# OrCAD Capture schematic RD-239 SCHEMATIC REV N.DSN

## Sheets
1 PAGE2: size A
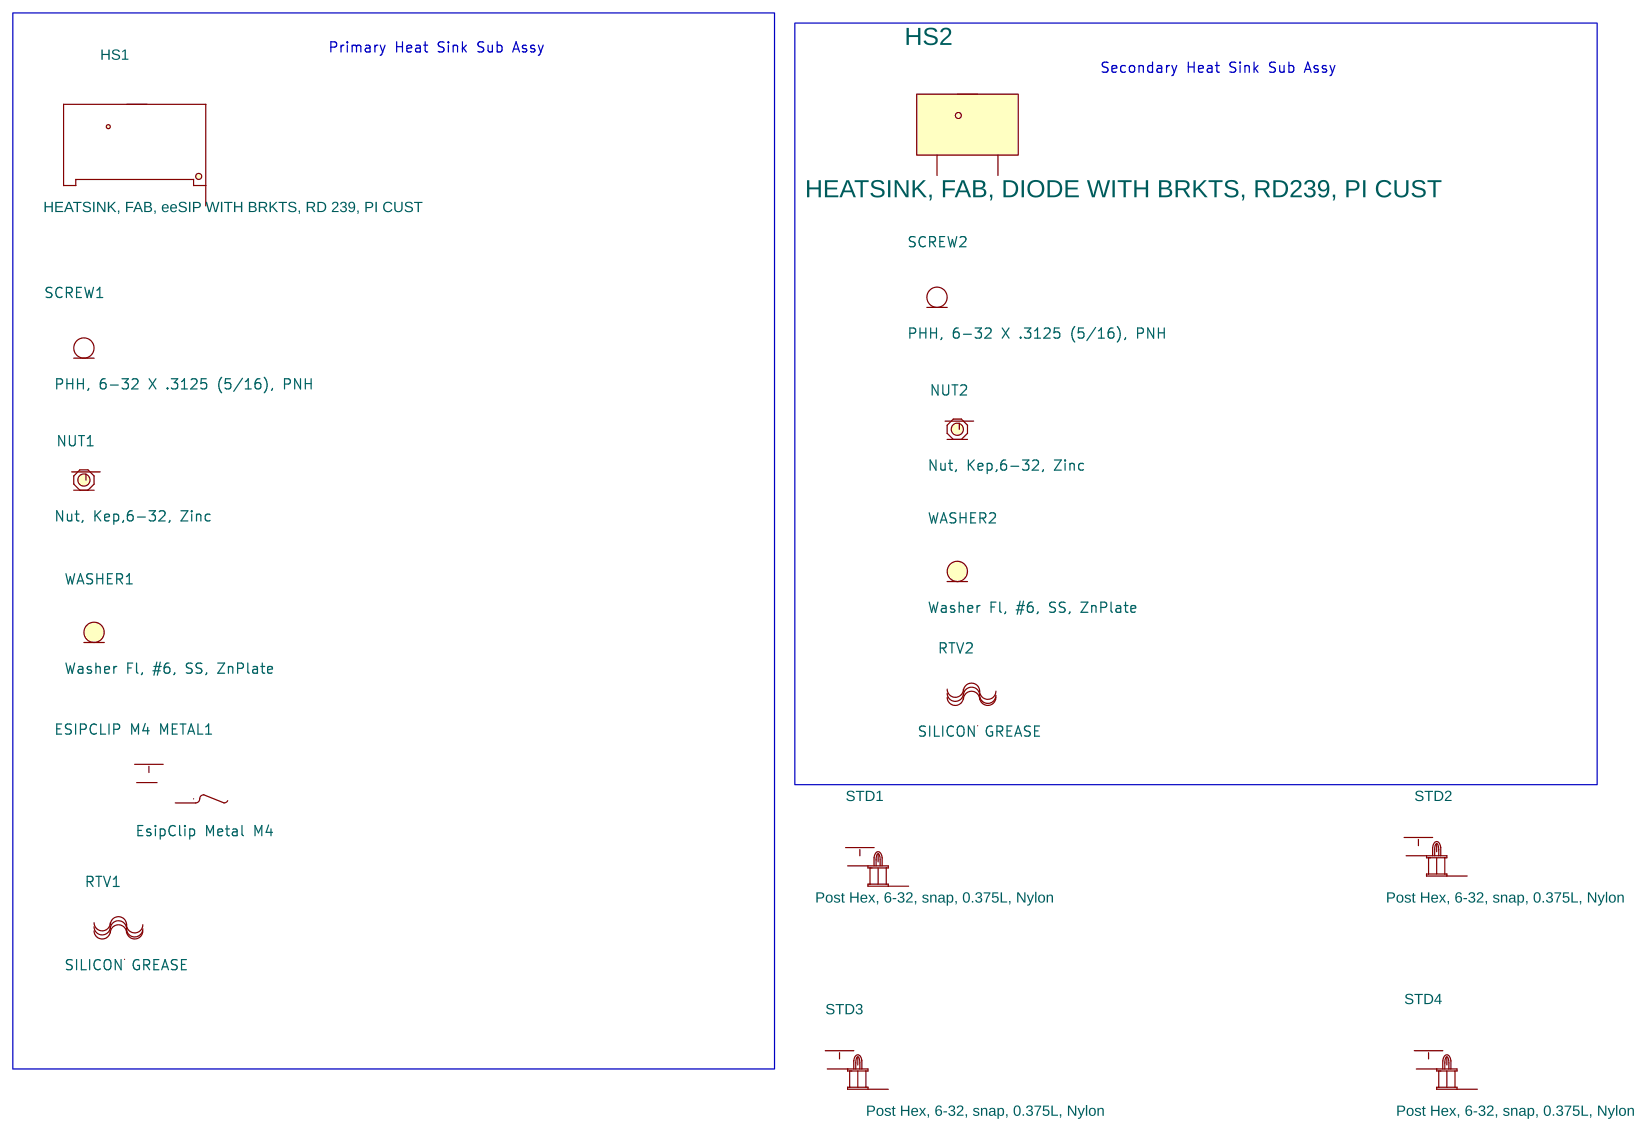
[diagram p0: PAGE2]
2 PAGE1: size B
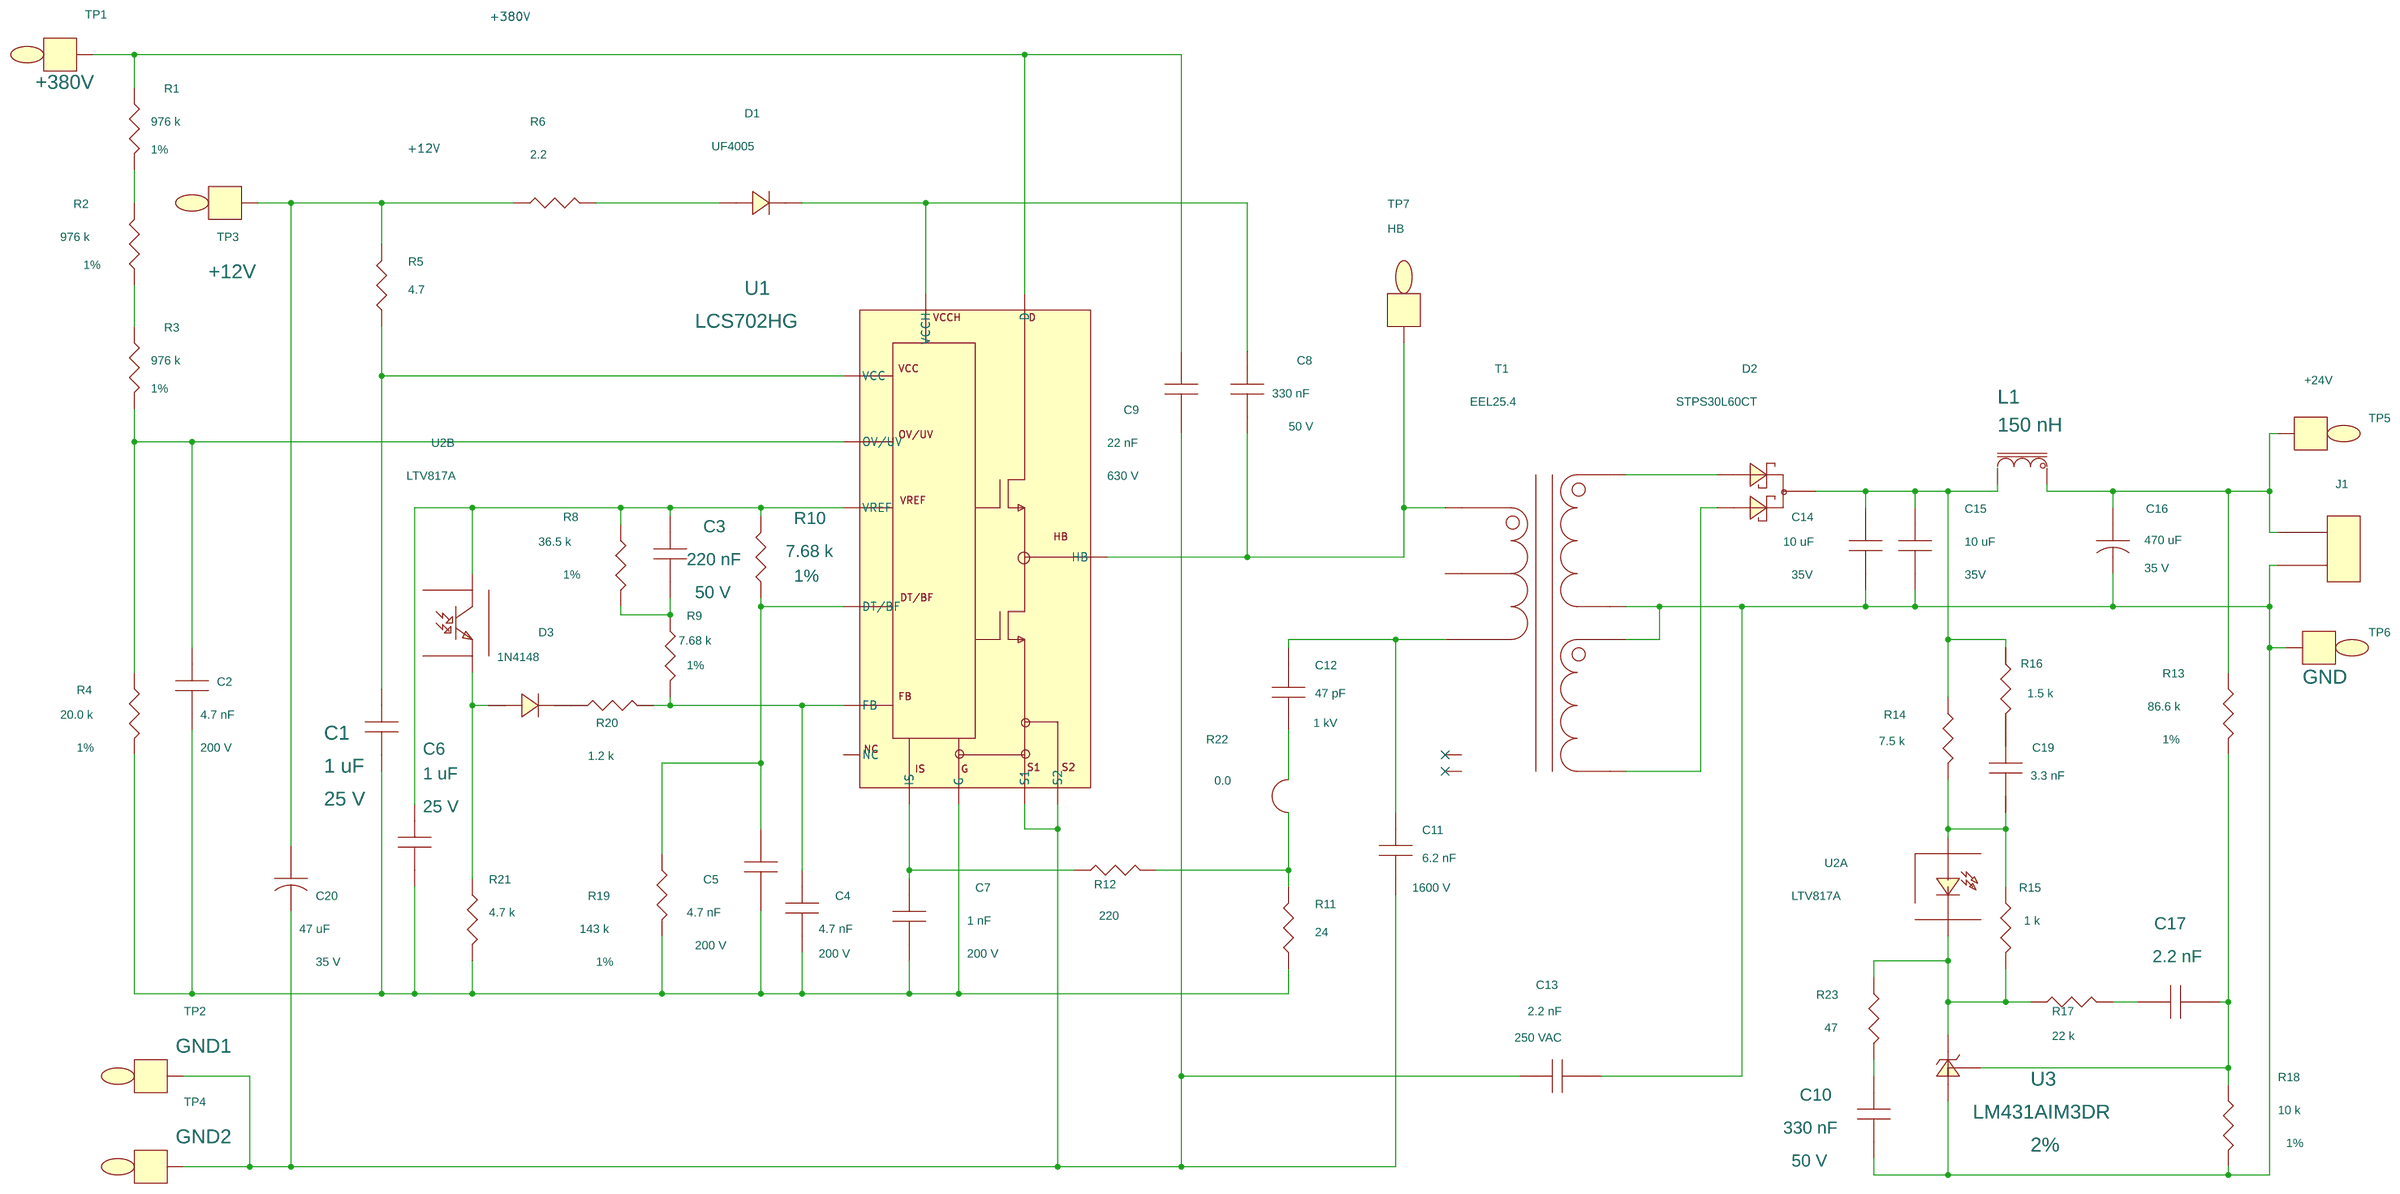
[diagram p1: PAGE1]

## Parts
sheet PAGE1
C1  1 uF  [pismc1206]
C2  4.7 nF  [pismc0805]
C3  220 nF  [pismc1206]
C4  4.7 nF  [pismc0805]
C5  4.7 nF  [pismc0805]
C6  1 uF  [pismc1206]
C7  1 nF  [pismc0805]
C8  330 nF  [pinpcaprad200x100200030]
C9  22 nF  [pismc1210]
C10  330 nF  [pinpcaprad200x100200030]
C11  6.2 nF  [PI_NP_CAPRAD709X197LS590D050]
C12  47 pF  [pinpcaprad180x160200030]
C13  2.2 nF  [pinpycaprad540x290ls400040]
C14  10 uF  [pismc1210]
C15  10 uF  [pismc1210]
C16  470 uF  [PI_POLCAP_CYL/D.400/LS.200/.040]
C17  2.2 nF  [pismc0805]
C19  3.3 nF  [PI_SM/C_0805]
C20  47 uF  [pipolcapclyd200ls80030]
D1  UF4005  [pidv200x110x040do41]
D2  STPS30L60CT
D3  1N4148  [PI_DAX/.375X.070/.030/DO_35]
J1  CON3
L1  150 nH  [PI_TOROID_2P_.150X.320/LS.150WX.150LX.050]
R1  976 k  [pismr1206]
R2  976 k  [pismr1206]
R3  976 k  [pi14wvresd100ls100d030]
R4  20.0 k  [pismr0805]
R5  4.7  [PI_SM/R_1206]
R6  2.2  [pismr1206]
R8  36.5 k  [pismr1206]
R9  7.68 k  [pismr1206]
R10  7.68 k  [pi14wvresd100ls100d030]
R11  24  [pismr1206]
R12  220  [pismr0805]
R13  86.6 k  [pi14wvresd100ls100d030]
R14  7.5 k  [pismr0805]
R15  1 k  [pismr0805]
R16  1.5 k  [PI_SM/R_0805]
R17  22 k  [pismr0805]
R18  10 k  [pismr0805]
R19  143 k  [pismr0805]
R20  1.2 k  [PI_SM/R_0805]
R21  4.7 k  [pismr1206]
R22  0.0  [pismr1206]
R23  47  [pismr0805]
T1  EEL25.4  [PI_BOBBIN_EEL25_4_11P]
TP1  +380V  [pitpkeystone125x125]
TP2  GND1  [pitpkeystone125x125]
TP3  +12V  [pitpkeystone125x125]
TP4  GND2  [pitpkeystone125x125]
TP5  +24V  [pitpkeystone125x125]
TP6  GND  [pitpkeystone125x125]
TP7  HB  [pitpkeystone125x125]
U1  LCS702HG  [PI_IC_ESIP16-13_OVAL_SLOT]
U2  LTV817A  [PI_DIP4]  (sections A,B)
U3  LM431AIM3DR  [pismsot23123]
sheet PAGE2
ESIPCLIP M4 METAL1  EsipClip Metal M4
HS1  HEATSINK, FAB, eeSIP WITH BRKTS, RD 239, PI CUST  [PI_HSK_RD239_PRI]
HS2  HEATSINK, FAB, DIODE WITH BRKTS, RD239, PI CUST  [PI_HSK_RD239_SEC]
NUT1  Nut, Kep,6-32, Zinc
NUT2  Nut, Kep,6-32, Zinc
RTV1  SILICON GREASE
RTV2  SILICON GREASE
SCREW1  PHH, 6-32 X .3125 (5/16), PNH
SCREW2  PHH, 6-32 X .3125 (5/16), PNH
STD1  Post Hex, 6-32, snap, 0.375L, Nylon
STD2  Post Hex, 6-32, snap, 0.375L, Nylon
STD3  Post Hex, 6-32, snap, 0.375L, Nylon
STD4  Post Hex, 6-32, snap, 0.375L, Nylon
WASHER1  Washer Fl, #6, SS, ZnPlate
WASHER2  Washer Fl, #6, SS, ZnPlate

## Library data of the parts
C1 = CAP_NP: Disp_Voltage: 25 V; Part Number: 20-00897-00; Tol: 10
C2 C5 = CAP_NP: COMPGROUP: 3; Disp_Voltage: 200 V; Layout PCB Footprint: PI_SM/C_0805; Part Number: 20-08570-00; Tol: 10
C3 = CAP_NP: COMPGROUP: 3; Disp_Voltage: 50 V; Layout PCB Footprint: PI_SM/C_1206; Part Number: 20-00188-00; Tol: 10
C4 = CAP_NP: COMPGROUP: 3; Disp_Voltage: 200 V; Part Number: 20-08570-00; Tol: 10
C6 = CAP_NP: COMPGROUP: 3; Disp_Voltage: 25 V; Part Number: 20-00897-00; Tol: 10
C7 = CAP_NP: COMPGROUP: 3; Disp_Voltage: 200 V; Layout PCB Footprint: PI_SM/C_0805; Part Number: 20-00737-00; Tol: 10
C8 = CAP_NP: COMPGROUP: 3; Disp_Voltage: 50 V; Part Number: 20-00935-00; Tol: 10
C9 = CAP_NP: Disp_Voltage: 630 V; Part Number: 20-00732-00; Tol: 10
C10 = CAP_NP: COMPGROUP: 3; Disp_Voltage: 50 V; Layout PCB Footprint: PI_SM/C_1206; Part Number: 20-00935-00; Tol: 10
C11 = CAP_NP: COMPGROUP: 4; Disp_Voltage: 1600 V; PCB Editor PCBFP: pi_np_caprad709x197ls590d050; Part Number: 20-00942-00; Tol: 5
C12 = CAP_NP: Disp_Voltage: 1 kV; Part Number: 20-00668-00; Tol: 5
C13 = CAP_NP: Disp_Voltage: 250 VAC; FPLIST: PI_NP_YCAP_RAD/.540X.290/LS.400/.040,PI_NP_YCAP_RAD/.540X.290/LS.400/.040_H; Part Number: 20-00376-00; Tol: 20
C14 C15 = CAP_NP: Disp_Voltage: 35V; Part Number: 23-00055-00; Tol: 10
C16 = CAP_POL: Disp_Voltage: 35 V; PCB Editor PCBFP: pipolcapcyld400ls200040; Part Number: 20-00048-00; Tol: 20
C17 = CAP_NP: COMPGROUP: 5; Disp_Voltage: 200 V; Layout PCB Footprint: PI_SM/C_0805; Part Number: 20-00761-00; Tol: 10
C19 = CAP_NP: COMPGROUP: 5; Disp_Voltage: 200 V; PCB Editor PCBFP: pismc0805; Part Number: 20-00956-00; Tol: 10
C20 = CAP_POL: Disp_Voltage: 35 V; Part Number: 20-00586-00; Tol: 20
D1 = DIODE: ALT_SYMBOLS: pidax475x125040do41,pidax390x125040do41; COMPGROUP: 3; FPLIST: PI_DV/.200X.110X.040/DO_41,PI_DAX/.475X.125/.040/DO_41,PI_DAX/.390X.125/.040/DO_41; Part Number: 15-00109-00
D2 = DS_DUAL_CK_A_AC: COMPGROUP: 4; FPLIST: PI_DV/TO220_3,PI_DV/TO220_3/VF1,PI_TO COMPATIBLES\PI_TO220AB_REC,PI_TO220AB/VF1/FLMT; Part Number: 15-00820-00
D3 = DIODE: FPLIST: PI_DV/.200X.080X.030/DO_35,PI_DAX/.375X.070/.030/DO_35,PI_DV/.100X.080X.030/DO_35; Part Number: 15-00083-00
J1 = CON2: Part Number: 35-00160-00
L1 = INDUCTOR1-2: FPLIST: PI_TOROID_2P_.150X.320/LS.150WX.150LX.050,PI_TOROID_2P_.150X.320/LS.150WX.150LX.050_1; Part Number: 32-00255-00
R1 R2 = R: Disp_Tol: 1%; Part Number: 05-00480-00; Tol: 1%
R3 = R: ALT_SYMBOLS: pi14wvresd100ls200d030,pi14wresd100ls400d030,pi14wresd100ls500d030; Disp_Tol: 1%; FPLIST: PI_1/4W_VRES/D.100/LS100/.030,PI_1/4W_VRES/D.100/LS200/.030,PI_1/4W_RES/D.100/LS.400/.030,PI_1/4W_RES/D.100/LS.500/.030; PCB Editor PCBFP: pi14wvresd100ls100d030,pi14wvresd100ls200d030,pi14wresd100ls400d030,pi14wresd100ls500d030; Part Number: 05-02263-00; Tol: 1%
R4 = R: Disp_Tol: 1%; Part Number: 05-00713-00; Tol: 1%
R5 = R: PCB Editor PCBFP: pismr1206; Part Number: 05-01296-00; Tol: 5%
R6 = R: Part Number: 05-01288-00; Tol: 5%
R8 = R: Disp_Tol: 1%; Part Number: 05-00343-00; Tol: 1%
R9 = R: Disp_Tol: 1%; Part Number: 05-00278-00; Tol: 1%
R10 = R: ALT_SYMBOLS: pi14wvresd100ls200d030,pi14wresd100ls400d030,pi14wresd100ls500d030; Disp_Tol: 1%; FPLIST: PI_1/4W_VRES/D.100/LS100/.030,PI_1/4W_VRES/D.100/LS200/.030,PI_1/4W_RES/D.100/LS.400/.030,PI_1/4W_RES/D.100/LS.500/.030; PCB Editor PCBFP: pi14wvresd100ls100d030,pi14wvresd100ls200d030,pi14wresd100ls400d030,pi14wresd100ls500d030; Part Number: 05-02061-00; Tol: 1%
R11 = R: Part Number: 05-01313-00; Tol: 5%
R12 = R: Part Number: 05-01503-00; Tol: 5%
R13 = R: ALT_SYMBOLS: pi14wvresd100ls200d030,pi14wresd100ls400d030,pi14wresd100ls500d030; COMPGROUP: 5; Disp_Tol: 1%; FPLIST: PI_1/4W_VRES/D.100/LS100/.030,PI_1/4W_VRES/D.100/LS200/.030,PI_1/4W_RES/D.100/LS.400/.030,PI_1/4W_RES/D.100/LS.500/.030; PCB Editor PCBFP: pi14wvresd100ls100d030,pi14wvresd100ls200d030,pi14wresd100ls400d030,pi14wresd100ls500d030; Part Number: 05-02162-00; Tol: 1%
R14 = R: COMPGROUP: 5; Part Number: 05-01540-00; Tol: 5%
R15 = R: COMPGROUP: 5; Part Number: 05-01519-00; Tol: 5%
R16 = R: COMPGROUP: 5; PCB Editor PCBFP: pismr0805; Part Number: 05-01523-00; Tol: 5%
R17 = R: COMPGROUP: 5; Part Number: 05-01551-00; Tol: 5%
R18 = R: COMPGROUP: 5; Disp_Tol: 1%; Part Number: 05-00684-00; Tol: 1%
R19 = R: Disp_Tol: 1%; Part Number: 05-00795-00; Tol: 1%
R20 = R: ALT_SYMBOLS: pi18wresd080ls300d030; PCB Editor PCBFP: pismr0805; Part Number: 05-01521-00; Tol: 5%
R21 = R: Part Number: 05-01368-00; Tol: 5%
R22 = JUMPER_1: Part Number: 05-03160-00; Tol: 5%
R23 = R: Part Number: 05-01487-00; Tol: 5%
T1 = BEEL_25.4_V_1PR_1S_C: Part Number: 25-00939-00
TP1 = TESTPOINT: Part Number: 35-00046-00
TP2 TP4 TP6 = TESTPOINT: Part Number: 35-00042-00
TP3 = TESTPOINT: Part Number: 35-00043-00
TP5 = TESTPOINT: Part Number: 35-00045-00
TP7 = TESTPOINT: Part Number: 35-00044-00
U1 = DEV_LC_SWITCH_Rev03: FPLIST: PI_IC_ESIP16-13_SLOT,PI_IC_ESIP16-13_SOCKET_SLOT_,PI_IC_ESIP16-13_OVAL_SLOT; Part Number: 10-00342-00
U2 = OPTO_A_B: COMPGROUP: 3; Part Number: 53-00008-00
U3 = TL431_SOT-23_CAR: Disp_Tol: 2%; Part Number: 45-00144-00; Tol: 2%
ESIPCLIP M4 METAL1 = EsipClip_Metal_M4: Part Number: 60-00042-00
HS1 = HS-RD239-eSIP: Part Number: 61-00058-01
HS2 = HS-RD239-Diode: Part Number: 61-00059-01
NUT1 NUT2 = NUT_HEX_4-40: Part Number: 75-00069-00
RTV1 RTV2 = RTV: Part Number: 66-00084-00
SCREW1 SCREW2 = SCR_6-32: Part Number: 75-00008-00
STD1-STD4 = POST_CRKT_BRD_6-32_HEX: Part Number: 76-00003-00
WASHER1 WASHER2 = WASH_FLAT_6: Part Number: 75-00167-00

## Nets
N4190778: C9.2 C11.2 C13.1 C20.2 TP2.1 TP4.1 U1.10(S1) U1.11(S2)
N4190786: C14.1 C15.1 D2.2(K) L1.2 R14.1 R16.1
N4190798: C8.2 T1.1 TP7.1 U1.13(HB)
N4190802: C16.1 J1.1 L1.1 R13.1 TP5.1
N4190814: C1.2 C2.2 C4.2 C5.2 C6.2 C7.2 R4.2 R11.1 R19.2 R21.2 U1.4(G)
N4190830: R11.2 R12.1 R22.1
N4190834: C9.1 R1.1 TP1.1 U1.16(D)
N4190856: R2.2 R3.1
N4190860: C17.2 R13.2 R18.1 U3.3(VREF)
N4190886: C10.2 C13.2 C14.2 C15.2 C16.2 J1.2 R18.2 T1.9 T1.10 TP6.1 U3.2(A)
N4190910: C11.1 C12.2 T1.5
N4190922: C3.1 C6.1 R8.1 R10.1 U1.3(VREF) U2.4(C)
N4191006: R1.2 R2.1
N4191076: R15.2 R17.2 R23.1 U2.2(C) U3.1(C)
N4191096: C17.1 R17.1
N4191496: D2.3(A2) T1.8
N4191500: D2.1(A1) T1.11
N4191534: C19.2 R14.2 R15.1 U2.1(A)
N4191864: C5.1 R10.2 R19.1 U1.7(DT/BF)
N4191970: C8.1 D1.1 U1.14(VCCH)
N4192000: C3.2 R8.2 R9.2
N4192016: C4.1 R9.1 R20.2 U1.6(FB)
N4192028: C2.1 R3.2 R4.1 U1.5(OV/UV)
N4192110: C20.1 R5.2 R6.1 TP3.1
N4192150: C1.1 R5.1 U1.1(VCC)
N4192154: C7.1 R12.2 U1.8(IS)
N4192166: D1.2 R6.2
N4220178: D3.2 R21.1 U2.3(E)
N4227486: C12.1 R22.2
N4248720: C10.1 R23.2
N4279234: D3.1 R20.1
N4279235: C19.1 R16.2

Not connected (* = marked no-connect by the designer): HS1 1; HS2 1 2; STD1 1; STD2 1; STD3 1; STD4 1; T1 2 6* 7*; U1 9(NC)

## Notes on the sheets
sheet 1
- Primary Heat Sink Sub Assy
- Secondary Heat Sink Sub Assy
sheet 2
- +380V
- +12V
